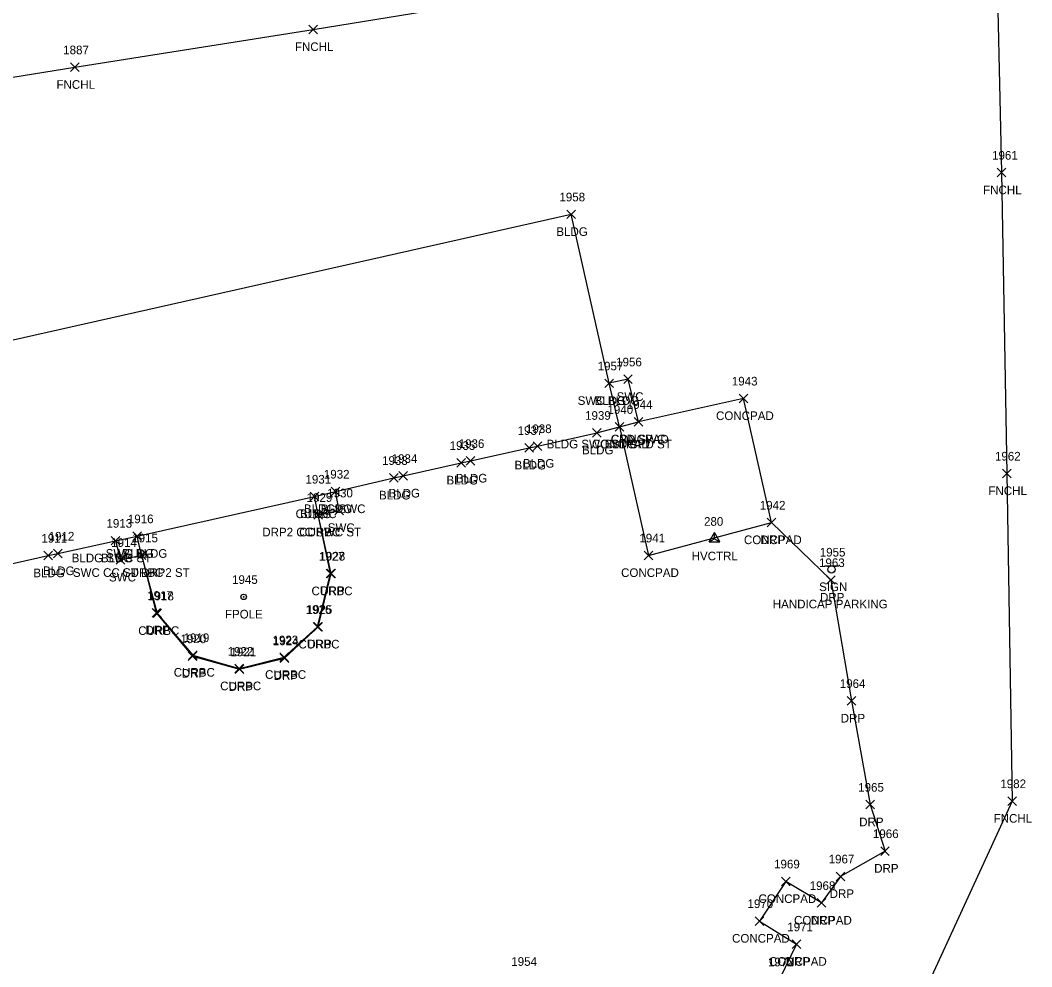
# Model space of a CAD drawing. Extents: x 1481523 to 1489083, y 884156 to 893756.
# Drawn here: x 1486897.7 to 1487131.9, y 888454.5 to 888673.5 of the extents above; entities that cross this region are included whole.
import ezdxf

# ---------------------------------------------------------------- set-up
doc = ezdxf.new("R2010")
doc.units = 0
for name, color, linetype in [('C_A', 7, 'Continuous'), ('C_I', 7, 'Continuous'), ('CPSM', 7, 'Continuous'), ('L_A', 7, 'Continuous'), ('L_I', 7, 'Continuous'), ('L_TIC', 7, 'Continuous'), ('LBC', 7, 'Continuous'), ('LFNC', 7, 'Continuous'), ('LFP', 7, 'Continuous'), ('LS', 7, 'Continuous'), ('R_A', 7, 'Continuous'), ('R_I', 7, 'Continuous'), ('R_TIC', 7, 'Continuous'), ('RC', 7, 'Continuous'), ('RDP', 7, 'Continuous'), ('RSW', 7, 'Continuous'), ('S_A', 7, 'Continuous'), ('S_C', 7, 'Continuous'), ('S_I', 7, 'Continuous'), ('SSGN', 7, 'Continuous')]:
    doc.layers.add(name, color=color, linetype=linetype)

msp = doc.modelspace()

# ---------------------------------------------------------------- linework, layer by layer
at = {"layer": 'CPSM'}
for p, q in [((1487057.24, 888552.81), (1487058.49, 888554.98)), ((1487057.24, 888552.81), (1487058.49, 888553.53)), ((1487059.74, 888552.81), (1487058.49, 888554.98)), ((1487058.49, 888553.53), (1487058.49, 888554.98)), ((1487058.49, 888553.53), (1487058.49, 888553.53)), ((1487058.49, 888553.53), (1487059.74, 888552.81)), ((1487057.24, 888552.81), (1487059.74, 888552.81))]:
    msp.add_line(p, q, dxfattribs=at)
at = {"layer": 'L_TIC'}
for points in [[(1486964.56, 888670.42), (1486966.56, 888672.42)], [(1486966.56, 888670.42), (1486964.56, 888672.42)], [(1486909.35, 888661.67), (1486911.35, 888663.67)], [(1486911.35, 888661.67), (1486909.35, 888663.67)], [(1487123.91, 888637.27), (1487125.91, 888639.27)], [(1487125.91, 888637.27), (1487123.91, 888639.27)], [(1487024.25, 888627.62), (1487026.25, 888629.62)], [(1487026.25, 888627.62), (1487024.25, 888629.62)], [(1487024.25, 888627.62), (1487026.25, 888629.62)], [(1487026.25, 888627.62), (1487024.25, 888629.62)], [(1487033.11, 888588.5), (1487035.11, 888590.5)], [(1487035.11, 888588.5), (1487033.11, 888590.5)], [(1487064.18, 888585), (1487066.18, 888587)], [(1487066.18, 888585), (1487064.18, 888587)], [(1487039.86, 888579.59), (1487041.86, 888581.59)], [(1487041.86, 888579.59), (1487039.86, 888581.59)], [(1487030.2, 888577.06), (1487032.2, 888579.06)], [(1487032.2, 888577.06), (1487030.2, 888579.06)], [(1487035.46, 888578.44), (1487037.46, 888580.44)], [(1487037.46, 888578.44), (1487035.46, 888580.44)], [(1487035.46, 888578.44), (1487037.46, 888580.44)], [(1487037.46, 888578.44), (1487035.46, 888580.44)], [(1487014.57, 888573.57), (1487016.57, 888575.57)], [(1487016.57, 888573.57), (1487014.57, 888575.57)], [(1487016.51, 888573.98), (1487018.51, 888575.98)], [(1487018.51, 888573.98), (1487016.51, 888575.98)], [(1486998.82, 888570.09), (1487000.82, 888572.09)], [(1487000.82, 888570.09), (1486998.82, 888572.09)], [(1487000.98, 888570.54), (1487002.98, 888572.54)], [(1487002.98, 888570.54), (1487000.98, 888572.54)], [(1487125.15, 888567.63), (1487127.15, 888569.63)], [(1487127.15, 888567.63), (1487125.15, 888569.63)], [(1486983.19, 888566.62), (1486985.19, 888568.62)], [(1486985.19, 888566.62), (1486983.19, 888568.62)], [(1486985.4, 888567.08), (1486987.4, 888569.08)], [(1486987.4, 888567.08), (1486985.4, 888569.08)], [(1486969.7, 888563.46), (1486971.7, 888565.46)], [(1486971.7, 888563.46), (1486969.7, 888565.46)], [(1486964.88, 888562.3), (1486966.88, 888564.3)], [(1486966.88, 888562.3), (1486964.88, 888564.3)], [(1487070.64, 888556.28), (1487072.64, 888558.28)], [(1487072.64, 888556.28), (1487070.64, 888558.28)], [(1486918.8, 888552.08), (1486920.8, 888554.08)], [(1486920.8, 888552.08), (1486918.8, 888554.08)], [(1486923.81, 888553.12), (1486925.81, 888555.12)], [(1486925.81, 888553.12), (1486923.81, 888555.12)], [(1486903.16, 888548.62), (1486905.16, 888550.62)], [(1486905.16, 888548.62), (1486903.16, 888550.62)], [(1486905.41, 888549.11), (1486907.41, 888551.11)], [(1486907.41, 888549.11), (1486905.41, 888551.11)], [(1487042.19, 888548.68), (1487044.19, 888550.68)], [(1487044.19, 888548.68), (1487042.19, 888550.68)], [(1487126.36, 888491.8), (1487128.36, 888493.8)], [(1487128.36, 888491.8), (1487126.36, 888493.8)], [(1487074.01, 888473.22), (1487076.01, 888475.22)], [(1487076.01, 888473.22), (1487074.01, 888475.22)], [(1487082.24, 888468.22), (1487084.24, 888470.22)], [(1487084.24, 888468.22), (1487082.24, 888470.22)], [(1487067.89, 888464.04), (1487069.89, 888466.04)], [(1487069.89, 888464.04), (1487067.89, 888466.04)], [(1487076.45, 888458.68), (1487078.45, 888460.68)], [(1487078.45, 888458.68), (1487076.45, 888460.68)]]:
    msp.add_lwpolyline(points, dxfattribs=at)
at = {"layer": 'LBC'}
for points in [[(1486843.17, 888587.71), (1487025.25, 888628.62)], [(1486890.77, 888546.64), (1486904.16, 888549.62), (1486906.41, 888550.11), (1486919.8, 888553.08), (1486924.81, 888554.12), (1486965.88, 888563.3), (1486970.7, 888564.46), (1486984.19, 888567.62), (1486986.4, 888568.08), (1486999.82, 888571.09), (1487001.98, 888571.54), (1487015.57, 888574.57), (1487017.51, 888574.98), (1487031.2, 888578.06), (1487036.46, 888579.44), (1487034.11, 888589.5), (1487025.25, 888628.62)]]:
    msp.add_lwpolyline(points, dxfattribs=at)
at = {"layer": 'LFNC'}
for points in [[(1487123.63, 888696.4), (1487124.91, 888638.27), (1487126.15, 888568.63), (1487127.36, 888492.8), (1487107.41, 888449.36), (1487090.77, 888413.6), (1487074.34, 888378.07), (1487054.02, 888334.46), (1487033.84, 888290.91), (1487013.45, 888247.02), (1487001.64, 888221.58), (1486993.21, 888204.38), (1486939.48, 888181.13), (1486867.52, 888150.81), (1486821.88, 888131.48), (1486777.19, 888112.51), (1486741.33, 888097.33), (1486705.19, 888082.4), (1486701.15, 888103.56), (1486696.51, 888133.19), (1486722.31, 888152.64)], [(1486611.93, 888614.86), (1486729.72, 888633.96), (1486821.77, 888648.41), (1486910.35, 888662.67), (1486965.56, 888671.42), (1487049.78, 888685.11)]]:
    msp.add_lwpolyline(points, dxfattribs=at)
at = {"layer": 'LFP'}
for radius in [0.625, 0.0833]:
    msp.add_circle((1486949.44, 888540.07), radius, dxfattribs=at)
at = {"layer": 'LS'}
for points in [[(1487036.46, 888579.44), (1487043.19, 888549.68), (1487071.64, 888557.28), (1487065.18, 888586), (1487040.86, 888580.59)], [(1487083.24, 888469.22), (1487075.01, 888474.22), (1487068.89, 888465.04), (1487077.45, 888459.68)]]:
    msp.add_lwpolyline(points, dxfattribs=at)
at = {"layer": 'R_TIC'}
for points in [[(1487033.11, 888588.5), (1487035.11, 888590.5)], [(1487035.11, 888588.5), (1487033.11, 888590.5)], [(1487037.44, 888589.43), (1487039.44, 888591.43)], [(1487039.44, 888589.43), (1487037.44, 888591.43)], [(1487039.86, 888579.59), (1487041.86, 888581.59)], [(1487041.86, 888579.59), (1487039.86, 888581.59)], [(1487035.46, 888578.44), (1487037.46, 888580.44)], [(1487037.46, 888578.44), (1487035.46, 888580.44)], [(1486969.7, 888563.46), (1486971.7, 888565.46)], [(1486971.7, 888563.46), (1486969.7, 888565.46)], [(1486964.88, 888562.3), (1486966.88, 888564.3)], [(1486966.88, 888562.3), (1486964.88, 888564.3)], [(1486965.72, 888558.07), (1486967.72, 888560.07)], [(1486967.72, 888558.07), (1486965.72, 888560.07)], [(1486965.72, 888558.07), (1486967.72, 888560.07)], [(1486967.72, 888558.07), (1486965.72, 888560.07)], [(1486965.72, 888558.07), (1486967.72, 888560.07)], [(1486967.72, 888558.07), (1486965.72, 888560.07)], [(1486970.56, 888559.1), (1486972.56, 888561.1)], [(1486972.56, 888559.1), (1486970.56, 888561.1)], [(1487070.64, 888556.28), (1487072.64, 888558.28)], [(1487072.64, 888556.28), (1487070.64, 888558.28)], [(1486918.8, 888552.08), (1486920.8, 888554.08)], [(1486920.8, 888552.08), (1486918.8, 888554.08)], [(1486923.81, 888553.12), (1486925.81, 888555.12)], [(1486925.81, 888553.12), (1486923.81, 888555.12)], [(1486924.77, 888548.7), (1486926.77, 888550.7)], [(1486926.77, 888548.7), (1486924.77, 888550.7)], [(1486924.77, 888548.7), (1486926.77, 888550.7)], [(1486926.77, 888548.7), (1486924.77, 888550.7)], [(1486924.77, 888548.7), (1486926.77, 888550.7)], [(1486926.77, 888548.7), (1486924.77, 888550.7)], [(1486919.9, 888547.64), (1486921.9, 888549.64)], [(1486921.9, 888547.64), (1486919.9, 888549.64)], [(1486968.56, 888544.45), (1486970.56, 888546.45)], [(1486970.56, 888544.45), (1486968.56, 888546.45)], [(1486968.7, 888544.49), (1486970.7, 888546.49)], [(1486970.7, 888544.49), (1486968.7, 888546.49)], [(1487084.41, 888542.98), (1487086.41, 888544.98)], [(1487086.41, 888542.98), (1487084.41, 888544.98)], [(1486928.22, 888535.39), (1486930.22, 888537.39)], [(1486930.22, 888535.39), (1486928.22, 888537.39)], [(1486928.45, 888535.26), (1486930.45, 888537.26)], [(1486930.45, 888535.26), (1486928.45, 888537.26)], [(1486965.55, 888532.13), (1486967.55, 888534.13)], [(1486967.55, 888532.13), (1486965.55, 888534.13)], [(1486965.71, 888532.15), (1486967.71, 888534.15)], [(1486967.71, 888532.15), (1486965.71, 888534.15)], [(1486936.59, 888525.36), (1486938.59, 888527.36)], [(1486938.59, 888525.36), (1486936.59, 888527.36)], [(1486936.68, 888525.61), (1486938.68, 888527.61)], [(1486938.68, 888525.61), (1486936.68, 888527.61)], [(1486957.82, 888525.09), (1486959.82, 888527.09)], [(1486959.82, 888525.09), (1486957.82, 888527.09)], [(1486957.91, 888524.86), (1486959.91, 888526.86)], [(1486959.91, 888524.86), (1486957.91, 888526.86)], [(1486947.42, 888522.46), (1486949.42, 888524.46)], [(1486949.42, 888522.46), (1486947.42, 888524.46)], [(1486947.5, 888522.31), (1486949.5, 888524.31)], [(1486949.5, 888522.31), (1486947.5, 888524.31)], [(1487089.21, 888514.99), (1487091.21, 888516.99)], [(1487091.21, 888514.99), (1487089.21, 888516.99)], [(1487093.48, 888490.98), (1487095.48, 888492.98)], [(1487095.48, 888490.98), (1487093.48, 888492.98)], [(1487096.95, 888480.24), (1487098.95, 888482.24)], [(1487098.95, 888480.24), (1487096.95, 888482.24)], [(1487086.64, 888474.38), (1487088.64, 888476.38)], [(1487088.64, 888474.38), (1487086.64, 888476.38)], [(1487082.24, 888468.22), (1487084.24, 888470.22)], [(1487084.24, 888468.22), (1487082.24, 888470.22)], [(1487076.45, 888458.68), (1487078.45, 888460.68)], [(1487078.45, 888458.68), (1487076.45, 888460.68)]]:
    msp.add_lwpolyline(points, dxfattribs=at)
at = {"layer": 'RC'}
msp.add_lwpolyline([(1486925.77, 888549.7), (1486929.45, 888536.26), (1486937.68, 888526.61), (1486948.42, 888523.46), (1486958.82, 888526.09), (1486966.55, 888533.13), (1486969.56, 888545.45), (1486966.72, 888559.07), (1486965.88, 888563.3)], dxfattribs=at)
at = {"layer": 'RDP'}
for points in [[(1486925.77, 888549.7), (1486929.22, 888536.39), (1486937.59, 888526.36), (1486948.5, 888523.31), (1486958.91, 888525.86), (1486966.71, 888533.15), (1486969.7, 888545.49), (1486966.72, 888559.07)], [(1487071.64, 888557.28), (1487085.41, 888543.98), (1487090.21, 888515.99), (1487094.48, 888491.98), (1487097.95, 888481.24), (1487087.64, 888475.38), (1487083.24, 888469.22)], [(1487077.45, 888459.68), (1487073.55, 888451.55), (1487070.71, 888445.5), (1487063.56, 888441.72), (1487054.26, 888439.24), (1487047.83, 888436.29), (1487045.07, 888432.18)]]:
    msp.add_lwpolyline(points, dxfattribs=at)
at = {"layer": 'RSW'}
for points in [[(1487036.46, 888579.44), (1487040.86, 888580.59), (1487038.44, 888590.43), (1487034.11, 888589.5)], [(1486966.72, 888559.07), (1486971.56, 888560.1), (1486970.7, 888564.46)], [(1486919.8, 888553.08), (1486920.9, 888548.64), (1486925.77, 888549.7), (1486924.81, 888554.12)]]:
    msp.add_lwpolyline(points, dxfattribs=at)
at = {"layer": 'SSGN'}
for p, q in [((1487083.9, 888547.26), (1487087.24, 888547.26)), ((1487085.55, 888546.43), (1487085.55, 888546.43))]:
    msp.add_line(p, q, dxfattribs=at)
msp.add_circle((1487085.55, 888546.43), 0.833, dxfattribs=at)

# ---------------------------------------------------------------- texts
at = {"layer": 'C_A'}
msp.add_text('HVCTRL', height=2, dxfattribs=at).set_placement((1487053.18, 888548.53))
at = {"layer": 'C_I'}
msp.add_text('280', height=2, dxfattribs=at).set_placement((1487056.04, 888556.53))
at = {"layer": 'L_A'}
for s, p in [('FNCHL', (1486961.31, 888666.42)), ('FNCHL', (1486906.1, 888657.67)), ('FNCHL', (1487120.66, 888633.27)), ('BLDG', (1487021.84, 888623.62)), ('BLDG', (1487021.84, 888623.62)), ('BLDG', (1487030.7, 888584.5)), ('CONCPAD', (1487058.82, 888581)), ('CONCPAD', (1487030.1, 888574.44)), ('BLDG', (1487033.05, 888574.44)), ('CONCPAD', (1487034.51, 888575.59)), ('BLDG', (1487027.79, 888573.06)), ('BLDG', (1487014.1, 888569.98)), ('BLDG', (1487012.16, 888569.57)), ('BLDG', (1486996.41, 888566.09)), ('BLDG', (1486998.57, 888566.54)), ('BLDG', (1486982.99, 888563.08)), ('FNCHL', (1487121.89, 888563.63)), ('BLDG', (1486980.78, 888562.62)), ('BLDG', (1486962.47, 888558.3)), ('BLDG', (1486967.29, 888559.46)), ('CONCPAD', (1487065.29, 888552.28)), ('BLDG', (1486921.4, 888549.12)), ('BLDG', (1486916.39, 888548.08)), ('BLDG', (1486900.75, 888544.62)), ('BLDG', (1486903, 888545.11)), ('CONCPAD', (1487036.84, 888544.68)), ('FPOLE', (1486945.11, 888535.07)), ('FNCHL', (1487123.11, 888487.8)), ('CONCPAD', (1487068.66, 888469.22)), ('CONCPAD', (1487076.89, 888464.22)), ('CONCPAD', (1487062.53, 888460.04)), ('CONCPAD', (1487071.09, 888454.68))]:
    msp.add_text(s, height=2, dxfattribs=at).set_placement(p)
at = {"layer": 'L_I'}
for s, p in [('1887', (1486907.66, 888665.67)), ('1961', (1487122.74, 888641.27)), ('1958', (1487022.56, 888631.62)), ('1958', (1487022.56, 888631.62)), ('1957', (1487031.41, 888592.5)), ('1943', (1487062.48, 888589)), ('1940', (1487033.68, 888582.44)), ('1940', (1487033.68, 888582.44)), ('1944', (1487038.17, 888583.59)), ('1939', (1487028.5, 888581.06)), ('1937', (1487012.88, 888577.57)), ('1938', (1487014.81, 888577.98)), ('1936', (1486999.23, 888574.54)), ('1935', (1486997.13, 888574.09)), ('1933', (1486981.49, 888570.62)), ('1934', (1486983.71, 888571.08)), ('1962', (1487123.41, 888571.63)), ('1932', (1486968.01, 888567.46)), ('1931', (1486963.75, 888566.3)), ('1942', (1487068.95, 888560.28)), ('1913', (1486917.67, 888556.08)), ('1916', (1486922.63, 888557.12)), ('1911', (1486902.6, 888552.62)), ('1912', (1486904.28, 888553.11)), ('1941', (1487041.07, 888552.68)), ('1945', (1486946.75, 888543.07)), ('1982', (1487124.66, 888495.8)), ('1969', (1487072.26, 888477.22)), ('1968', (1487080.5, 888472.22)), ('1970', (1487066.11, 888468.04)), ('1971', (1487075.32, 888462.68)), ('1954', (1487011.41, 888454.67))]:
    msp.add_text(s, height=2, dxfattribs=at).set_placement(p)
at = {"layer": 'R_A'}
for s, p in [('SWC BLDG', (1487026.79, 888584.5)), ('SWC', (1487035.8, 888585.43)), ('BLDG SWC ST CPD ST', (1487019.6, 888574.44)), ('CPD SWC', (1487034.44, 888575.59)), ('CURBC', (1486961.46, 888558.3)), ('BLDG SWC', (1486963.39, 888559.46)), ('DRP2 CC SWC ST', (1486953.75, 888554.07)), ('CURBC', (1486962.3, 888554.07)), ('DRP', (1486964.2, 888554.07)), ('SWC', (1486968.92, 888555.1)), ('DRP', (1487069.13, 888552.28)), ('SWC BLDG', (1486917.5, 888549.12)), ('BLDG SWC ST', (1486909.62, 888548.08)), ('SWC CC ST DRP2 ST', (1486909.9, 888544.7)), ('CURBC', (1486921.35, 888544.7)), ('DRP', (1486923.26, 888544.7)), ('SWC', (1486918.26, 888543.64)), ('CURBC', (1486965.15, 888540.45)), ('DRP', (1486967.19, 888540.49)), ('DRP', (1487082.9, 888538.98)), ('CURBC', (1486925.03, 888531.26)), ('DRP', (1486926.71, 888531.39)), ('CURBC', (1486962.13, 888528.13)), ('DRP', (1486964.2, 888528.15)), ('CURBC', (1486933.26, 888521.61)), ('DRP', (1486935.08, 888521.36)), ('CURBC', (1486954.4, 888521.09)), ('DRP', (1486956.4, 888520.86)), ('CURBC', (1486944, 888518.46)), ('DRP', (1486945.98, 888518.31)), ('DRP', (1487087.7, 888510.99)), ('DRP', (1487091.97, 888486.98)), ('DRP', (1487095.44, 888476.24)), ('DRP', (1487085.13, 888470.38)), ('DRP', (1487080.73, 888464.22)), ('DRP', (1487074.94, 888454.68))]:
    msp.add_text(s, height=2, dxfattribs=at).set_placement(p)
at = {"layer": 'R_I'}
for s, p in [('1956', (1487035.69, 888593.43)), ('1957', (1487031.41, 888592.5)), ('1940', (1487033.68, 888582.44)), ('1944', (1487038.17, 888583.59)), ('1932', (1486968.01, 888567.46)), ('1931', (1486963.75, 888566.3)), ('1930', (1486968.78, 888563.1)), ('1929', (1486964.02, 888562.07)), ('1929', (1486964.02, 888562.07)), ('1929', (1486964.02, 888562.07)), ('1942', (1487068.95, 888560.28)), ('1913', (1486917.67, 888556.08)), ('1916', (1486922.63, 888557.12)), ('1914', (1486918.77, 888551.64)), ('1915', (1486923.64, 888552.7)), ('1915', (1486923.64, 888552.7)), ('1915', (1486923.64, 888552.7)), ('1927', (1486966.87, 888548.45)), ('1928', (1486967.01, 888548.49)), ('1963', (1487082.67, 888546.98)), ('1917', (1486927.09, 888539.39)), ('1918', (1486927.32, 888539.26)), ('1926', (1486963.8, 888536.13)), ('1925', (1486964.02, 888536.15)), ('1920', (1486934.81, 888529.36)), ('1919', (1486935.54, 888529.61)), ('1923', (1486956.12, 888529.09)), ('1924', (1486956.22, 888528.86)), ('1922', (1486945.73, 888526.46)), ('1921', (1486946.37, 888526.31)), ('1964', (1487087.47, 888518.99)), ('1965', (1487091.74, 888494.98)), ('1966', (1487095.15, 888484.24)), ('1967', (1487084.9, 888478.38)), ('1968', (1487080.5, 888472.22)), ('1971', (1487075.32, 888462.68)), ('1972', (1487070.85, 888454.55))]:
    msp.add_text(s, height=2, dxfattribs=at).set_placement(p)
at = {"layer": 'S_A'}
msp.add_text('SIGN', height=2, dxfattribs=at).set_placement((1487082.69, 888541.41))
at = {"layer": 'S_C'}
msp.add_text('HANDICAP PARKING', height=2, dxfattribs=at).set_placement((1487071.96, 888537.41))
at = {"layer": 'S_I'}
msp.add_text('1955', height=2, dxfattribs=at).set_placement((1487082.84, 888549.41))

doc.saveas('drawing.dxf')
